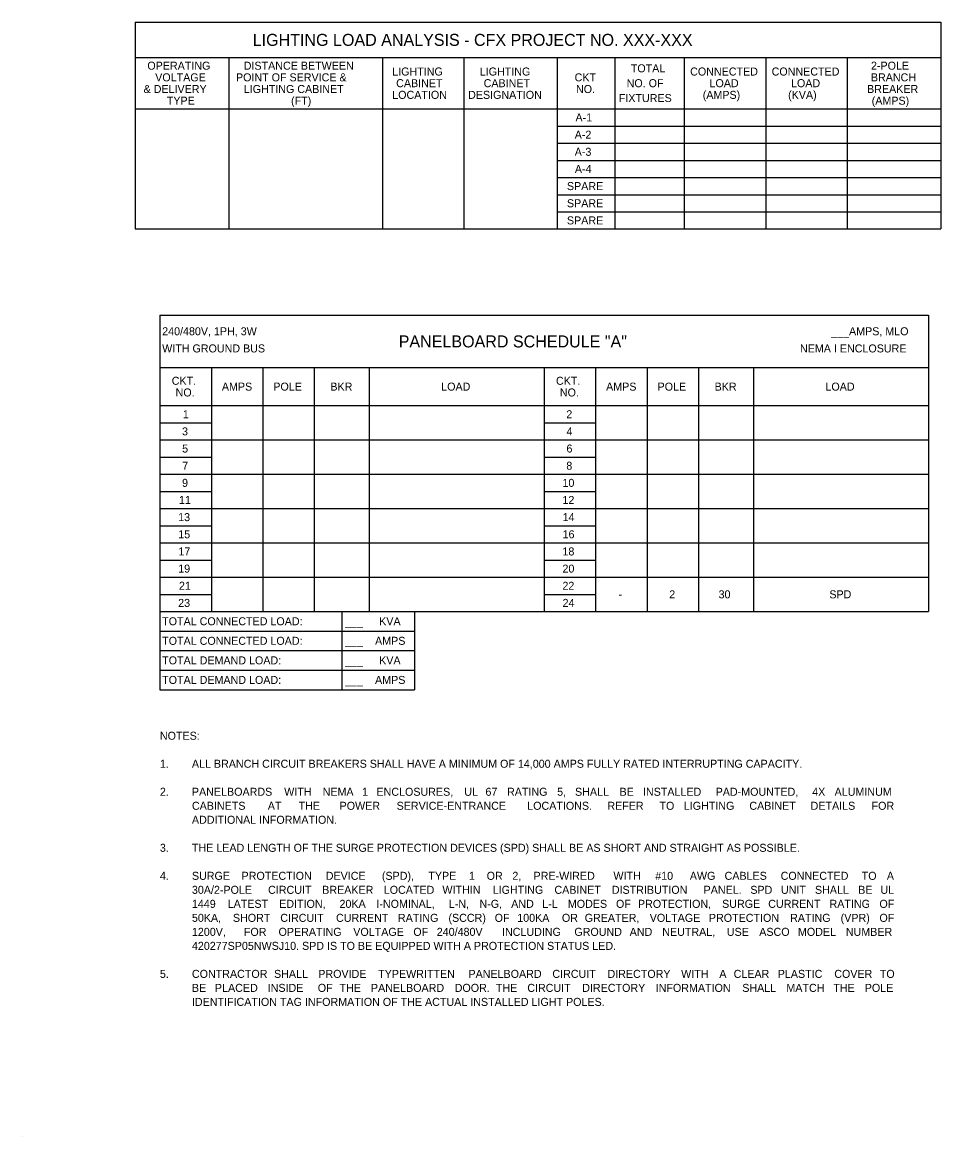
# Model space of a CAD drawing. Extents: x 856079 to 2148480, y 462635 to 2147771.
# Drawn here: x 2148464.67 to 2148472.7, y 2147761.57 to 2147771.31 of the extents above; entities that cross this region are included whole.
import ezdxf

# ---------------------------------------------------------------- set-up
doc = ezdxf.new("R2010")
doc.units = 0
for name, color, linetype in [('AdhocPoint_dp', 7, 'Continuous'), ('FLMap5', 7, 'Continuous'), ('SumBoxBorder_dp', 7, 'Continuous'), ('SumBoxLines_dp', 7, 'Continuous'), ('TextNotes', 7, 'Continuous')]:
    doc.layers.add(name, color=color, linetype=linetype)

msp = doc.modelspace()

# ---------------------------------------------------------------- linework, layer by layer
at = {"layer": 'AdhocPoint_dp'}
msp.add_line((2148464.6682, 2147761.5674), (2148464.6682, 2147761.5674), dxfattribs=at)
at = {"layer": 'SumBoxBorder_dp'}
for p, q in [((2148465.6565, 2147771.3129), (2148472.699, 2147771.3129)), ((2148465.6565, 2147771.3129), (2148465.6565, 2147769.5054)), ((2148472.699, 2147771.3129), (2148472.699, 2147769.5054)), ((2148465.6565, 2147771.0054), (2148472.699, 2147771.0054)), ((2148465.6565, 2147771.0054), (2148472.699, 2147771.0054)), ((2148465.6565, 2147769.5054), (2148472.699, 2147769.5054)), ((2148465.8715, 2147768.7509), (2148472.5915, 2147768.7509)), ((2148465.8715, 2147768.7509), (2148465.8715, 2147765.4764)), ((2148472.5915, 2147768.7509), (2148472.5915, 2147766.1604)), ((2148465.8715, 2147768.2934), (2148472.5915, 2147768.2934)), ((2148465.8715, 2147768.2934), (2148472.5915, 2147768.2934)), ((2148465.8715, 2147766.1604), (2148472.5915, 2147766.1604)), ((2148465.8715, 2147766.1604), (2148472.5915, 2147766.1604)), ((2148467.4615, 2147766.1604), (2148467.4615, 2147765.4764)), ((2148467.4615, 2147766.1604), (2148467.4615, 2147765.4764)), ((2148468.099, 2147766.1604), (2148468.099, 2147765.4764)), ((2148468.099, 2147766.1604), (2148468.099, 2147765.4764)), ((2148465.8715, 2147765.9894), (2148468.099, 2147765.9894)), ((2148465.8715, 2147765.9894), (2148468.099, 2147765.9894)), ((2148465.8715, 2147765.8184), (2148468.099, 2147765.8184)), ((2148465.8715, 2147765.8184), (2148468.099, 2147765.8184)), ((2148465.8715, 2147765.6474), (2148468.099, 2147765.6474)), ((2148465.8715, 2147765.6474), (2148468.099, 2147765.6474)), ((2148465.8715, 2147765.4764), (2148468.099, 2147765.4764))]:
    msp.add_line(p, q, dxfattribs=at)
at = {"layer": 'SumBoxLines_dp'}
for p, q in [((2148466.474, 2147771.0054), (2148466.474, 2147769.5054)), ((2148466.474, 2147771.0054), (2148466.474, 2147769.5054)), ((2148467.8165, 2147771.0054), (2148467.8165, 2147769.5054)), ((2148467.8165, 2147771.0054), (2148467.8165, 2147769.5054)), ((2148468.529, 2147771.0054), (2148468.529, 2147769.5054)), ((2148468.529, 2147771.0054), (2148468.529, 2147769.5054)), ((2148469.3465, 2147771.0054), (2148469.3465, 2147769.5054)), ((2148469.3465, 2147771.0054), (2148469.3465, 2147769.5054)), ((2148469.849, 2147771.0054), (2148469.849, 2147769.5054)), ((2148469.849, 2147771.0054), (2148469.849, 2147769.5054)), ((2148470.4565, 2147771.0054), (2148470.4565, 2147769.5054)), ((2148470.4565, 2147771.0054), (2148470.4565, 2147769.5054)), ((2148471.169, 2147771.0054), (2148471.169, 2147769.5054)), ((2148471.169, 2147771.0054), (2148471.169, 2147769.5054)), ((2148471.8815, 2147771.0054), (2148471.8815, 2147769.5054)), ((2148471.8815, 2147771.0054), (2148471.8815, 2147769.5054)), ((2148465.6565, 2147770.5554), (2148472.699, 2147770.5554)), ((2148465.6565, 2147770.5554), (2148472.699, 2147770.5554)), ((2148469.3465, 2147770.4054), (2148472.699, 2147770.4054)), ((2148469.3465, 2147770.4054), (2148472.699, 2147770.4054)), ((2148469.3465, 2147770.2554), (2148472.699, 2147770.2554)), ((2148469.3465, 2147770.2554), (2148472.699, 2147770.2554)), ((2148469.3465, 2147770.1054), (2148472.699, 2147770.1054)), ((2148469.3465, 2147770.1054), (2148472.699, 2147770.1054)), ((2148469.3465, 2147769.9554), (2148472.699, 2147769.9554)), ((2148469.3465, 2147769.9554), (2148472.699, 2147769.9554)), ((2148469.3465, 2147769.8054), (2148472.699, 2147769.8054)), ((2148469.3465, 2147769.8054), (2148472.699, 2147769.8054)), ((2148469.3465, 2147769.6554), (2148472.699, 2147769.6554)), ((2148469.3465, 2147769.6554), (2148472.699, 2147769.6554)), ((2148466.3215, 2147768.2934), (2148466.3215, 2147766.1604)), ((2148466.3215, 2147768.2934), (2148466.3215, 2147766.1604)), ((2148466.7715, 2147768.2934), (2148466.7715, 2147766.1604)), ((2148466.7715, 2147768.2934), (2148466.7715, 2147766.1604)), ((2148467.2215, 2147768.2934), (2148467.2215, 2147766.1604)), ((2148467.2215, 2147768.2934), (2148467.2215, 2147766.1604)), ((2148467.7015, 2147768.2934), (2148467.7015, 2147766.1604)), ((2148467.7015, 2147768.2934), (2148467.7015, 2147766.1604)), ((2148469.2315, 2147768.2934), (2148469.2315, 2147766.1604)), ((2148469.6815, 2147768.2934), (2148469.6815, 2147766.1604)), ((2148469.6815, 2147768.2934), (2148469.6815, 2147766.1604)), ((2148470.1315, 2147768.2934), (2148470.1315, 2147766.1604)), ((2148470.1315, 2147768.2934), (2148470.1315, 2147766.1604)), ((2148470.5815, 2147768.2934), (2148470.5815, 2147766.1604)), ((2148470.5815, 2147768.2934), (2148470.5815, 2147766.1604)), ((2148471.0615, 2147768.2934), (2148471.0615, 2147766.1604)), ((2148471.0615, 2147768.2934), (2148471.0615, 2147766.1604)), ((2148465.8715, 2147767.9604), (2148472.5915, 2147767.9604)), ((2148465.8715, 2147767.9604), (2148472.5915, 2147767.9604)), ((2148469.2315, 2147767.9604), (2148469.2315, 2147766.1604)), ((2148465.8715, 2147767.8104), (2148466.3215, 2147767.8104)), ((2148469.2315, 2147767.8104), (2148469.6815, 2147767.8104)), ((2148465.8715, 2147767.6604), (2148472.5915, 2147767.6604)), ((2148465.8715, 2147767.6604), (2148472.5915, 2147767.6604)), ((2148465.8715, 2147767.5104), (2148466.3215, 2147767.5104)), ((2148465.8715, 2147767.5104), (2148466.3215, 2147767.5104)), ((2148469.2315, 2147767.5104), (2148469.6815, 2147767.5104)), ((2148469.2315, 2147767.5104), (2148469.6815, 2147767.5104)), ((2148465.8715, 2147767.3604), (2148472.5915, 2147767.3604)), ((2148466.3215, 2147767.3604), (2148469.2315, 2147767.3604)), ((2148469.6815, 2147767.3604), (2148472.5915, 2147767.3604)), ((2148465.8715, 2147767.2104), (2148466.3215, 2147767.2104)), ((2148465.8715, 2147767.2104), (2148466.3215, 2147767.2104)), ((2148469.2315, 2147767.2104), (2148469.6815, 2147767.2104)), ((2148469.2315, 2147767.2104), (2148469.6815, 2147767.2104)), ((2148465.8715, 2147767.0604), (2148472.5915, 2147767.0604)), ((2148465.8715, 2147767.0604), (2148472.5915, 2147767.0604)), ((2148465.8715, 2147766.9104), (2148466.3215, 2147766.9104)), ((2148469.2315, 2147766.9104), (2148469.6815, 2147766.9104)), ((2148465.8715, 2147766.7604), (2148472.5915, 2147766.7604)), ((2148465.8715, 2147766.7604), (2148472.5915, 2147766.7604)), ((2148465.8715, 2147766.6104), (2148466.3215, 2147766.6104)), ((2148465.8715, 2147766.6104), (2148466.3215, 2147766.6104)), ((2148469.2315, 2147766.6104), (2148469.6815, 2147766.6104)), ((2148469.2315, 2147766.6104), (2148469.6815, 2147766.6104)), ((2148465.8715, 2147766.4604), (2148472.5915, 2147766.4604)), ((2148466.3215, 2147766.4604), (2148469.2315, 2147766.4604)), ((2148469.6815, 2147766.4604), (2148472.5915, 2147766.4604)), ((2148465.8715, 2147766.3104), (2148466.3215, 2147766.3104)), ((2148465.8715, 2147766.3104), (2148466.3215, 2147766.3104)), ((2148469.2315, 2147766.3104), (2148469.6815, 2147766.3104)), ((2148469.2315, 2147766.3104), (2148469.6815, 2147766.3104))]:
    msp.add_line(p, q, dxfattribs=at)

# ---------------------------------------------------------------- texts
at = {"layer": 'FLMap5'}
for s, height, p in [('LIGHTING LOAD ANALYSIS - CFX PROJECT NO. XXX-XXX', 0.105, (2148466.6829, 2147771.1067)), ('OPERATING', 0.07, (2148465.7617, 2147770.8984)), ('DISTANCE BETWEEN', 0.07, (2148466.6045, 2147770.8984)), ('LIGHTING', 0.07, (2148467.9031, 2147770.8474)), ('LIGHTING', 0.07, (2148468.6681, 2147770.8474)), ('TOTAL', 0.07, (2148469.9891, 2147770.8754)), ('CONNECTED', 0.07, (2148470.5081, 2147770.8474)), ('CONNECTED', 0.07, (2148471.2206, 2147770.8474)), ('2-POLE', 0.07, (2148472.0893, 2147770.8984)), ('VOLTAGE', 0.07, (2148465.8304, 2147770.7964)), ('POINT OF SERVICE &', 0.07, (2148466.5368, 2147770.7964)), ('CABINET', 0.07, (2148467.9374, 2147770.7454)), ('CABINET', 0.07, (2148468.7024, 2147770.7454)), ('CKT', 0.07, (2148469.4979, 2147770.7964)), ('NO. OF', 0.07, (2148469.9528, 2147770.7454)), ('LOAD', 0.07, (2148470.6775, 2147770.7454)), ('LOAD', 0.07, (2148471.39, 2147770.7454)), ('BRANCH', 0.07, (2148472.0883, 2147770.7964)), ('& DELIVERY', 0.07, (2148465.7289, 2147770.6944)), ('LIGHTING CABINET', 0.07, (2148466.605, 2147770.6944)), ('LOCATION', 0.07, (2148467.9031, 2147770.6434)), ('DESIGNATION', 0.07, (2148468.5664, 2147770.6434)), ('NO.', 0.07, (2148469.5101, 2147770.6944)), ('(AMPS)', 0.07, (2148470.6182, 2147770.6434)), ('(KVA)', 0.07, (2148471.3646, 2147770.6434)), ('BREAKER', 0.07, (2148472.0553, 2147770.6944)), ('TYPE', 0.07, (2148465.932, 2147770.5924)), ('(FT)', 0.07, (2148467.0184, 2147770.5924)), ('FIXTURES', 0.07, (2148469.8842, 2147770.6154)), ('(AMPS)', 0.07, (2148472.0957, 2147770.5924)), ('A-1', 0.07, (2148469.5054, 2147770.4454)), ('A-2', 0.07, (2148469.4986, 2147770.2954)), ('A-3', 0.07, (2148469.4986, 2147770.1454)), ('A-4', 0.07, (2148469.5, 2147769.9954)), ('SPARE', 0.07, (2148469.4306, 2147769.8454)), ('SPARE', 0.07, (2148469.4306, 2147769.6954)), ('SPARE', 0.07, (2148469.4306, 2147769.5454)), ('240/480V, 1PH, 3W', 0.07, (2148465.8915, 2147768.5759)), ('___AMPS, MLO', 0.07, (2148471.7412, 2147768.5759)), ('PANELBOARD SCHEDULE "A"', 0.105, (2148467.9596, 2147768.4697)), ('WITH GROUND BUS', 0.07, (2148465.8915, 2147768.4259)), ('NEMA I ENCLOSURE', 0.07, (2148471.4688, 2147768.4259)), ('CKT.', 0.07, (2148465.975, 2147768.1429)), ('AMPS', 0.07, (2148466.4134, 2147768.0919)), ('POLE', 0.07, (2148466.8633, 2147768.0919)), ('BKR', 0.07, (2148467.3621, 2147768.0919)), ('LOAD', 0.07, (2148468.3313, 2147768.0919)), ('CKT.', 0.07, (2148469.335, 2147768.1429)), ('AMPS', 0.07, (2148469.7734, 2147768.0919)), ('POLE', 0.07, (2148470.2233, 2147768.0919)), ('BKR', 0.07, (2148470.7221, 2147768.0919)), ('LOAD', 0.07, (2148471.6913, 2147768.0919)), ('NO.', 0.07, (2148466.0089, 2147768.0409)), ('NO.', 0.07, (2148469.3689, 2147768.0409)), ('1', 0.07, (2148466.0719, 2147767.8504)), ('2', 0.07, (2148469.4251, 2147767.8504)), ('3', 0.07, (2148466.0651, 2147767.7004)), ('4', 0.07, (2148469.4265, 2147767.7004)), ('5', 0.07, (2148466.066, 2147767.5504)), ('6', 0.07, (2148469.4265, 2147767.5504)), ('7', 0.07, (2148466.0671, 2147767.4004)), ('8', 0.07, (2148469.4254, 2147767.4004)), ('9', 0.07, (2148466.0655, 2147767.2504)), ('10', 0.07, (2148469.3918, 2147767.2504)), ('11', 0.07, (2148466.038, 2147767.1004)), ('12', 0.07, (2148469.3913, 2147767.1004)), ('13', 0.07, (2148466.0312, 2147766.9504)), ('14', 0.07, (2148469.3926, 2147766.9504)), ('15', 0.07, (2148466.0321, 2147766.8004)), ('16', 0.07, (2148469.3927, 2147766.8004)), ('17', 0.07, (2148466.0333, 2147766.6504)), ('18', 0.07, (2148469.3915, 2147766.6504)), ('19', 0.07, (2148466.0316, 2147766.5004)), ('20', 0.07, (2148469.3918, 2147766.5004)), ('21', 0.07, (2148466.038, 2147766.3504)), ('22', 0.07, (2148469.3913, 2147766.3504)), ('2', 0.07, (2148470.3251, 2147766.2754)), ('30', 0.07, (2148470.7568, 2147766.2754)), ('SPD', 0.07, (2148471.7252, 2147766.2754)), ('23', 0.07, (2148466.0312, 2147766.2004)), ('24', 0.07, (2148469.3926, 2147766.2004)), ('-', 0.07, (2148469.883, 2147766.2754)), ('TOTAL CONNECTED LOAD:', 0.07, (2148465.8915, 2147766.0399)), ('___', 0.07, (2148467.4905, 2147766.0399)), ('KVA', 0.07, (2148467.7889, 2147766.0399)), ('TOTAL CONNECTED LOAD:', 0.07, (2148465.8915, 2147765.8689)), ('AMPS', 0.07, (2148467.7529, 2147765.8689)), ('___', 0.07, (2148467.4905, 2147765.8689)), ('TOTAL DEMAND LOAD:', 0.07, (2148465.8915, 2147765.6979)), ('KVA', 0.07, (2148467.7889, 2147765.6979)), ('___', 0.07, (2148467.4905, 2147765.6979)), ('TOTAL DEMAND LOAD:', 0.07, (2148465.8915, 2147765.5269)), ('AMPS', 0.07, (2148467.7529, 2147765.5269)), ('___', 0.07, (2148467.4905, 2147765.5269))]:
    msp.add_text(s, height=height, dxfattribs=at).set_placement(p)
at = {"layer": 'TextNotes'}
for s, p in [('NOTES:', (2148465.8715, 2147765.0389)), ('1.', (2148465.8715, 2147764.7939)), ('ALL BRANCH CIRCUIT BREAKERS SHALL HAVE A MINIMUM OF 14,000 AMPS FULLY RATED INTERRUPTING CAPACITY.', (2148466.1515, 2147764.7939)), ('2.', (2148465.8715, 2147764.5489)), ('PANELBOARDS ', (2148466.1515, 2147764.5489)), ('WITH ', (2148466.9584, 2147764.5489)), ('NEMA ', (2148467.2946, 2147764.5489)), ('1 ', (2148467.6395, 2147764.5489)), ('ENCLOSURES, ', (2148467.7652, 2147764.5489)), ('UL ', (2148468.5329, 2147764.5489)), ('67 ', (2148468.7183, 2147764.5489)), ('RATING ', (2148468.9068, 2147764.5489)), ('5, ', (2148469.3451, 2147764.5489)), ('SHALL ', (2148469.5014, 2147764.5489)), ('BE ', (2148469.8908, 2147764.5489)), ('INSTALLED ', (2148470.0957, 2147764.5489)), ('PAD-MOUNTED, ', (2148470.7311, 2147764.5489)), ('4X ', (2148471.5752, 2147764.5489)), ('ALUMINUM ', (2148471.7711, 2147764.5489)), ('CABINETS ', (2148466.1515, 2147764.4264)), ('AT ', (2148466.8149, 2147764.4264)), ('THE ', (2148467.085, 2147764.4264)), ('POWER ', (2148467.4429, 2147764.4264)), ('SERVICE-ENTRANCE ', (2148467.9412, 2147764.4264)), ('LOCATIONS. ', (2148469.0833, 2147764.4264)), (' REFER ', (2148469.758, 2147764.4264)), ('TO ', (2148470.2398, 2147764.4264)), ('LIGHTING ', (2148470.4525, 2147764.4264)), ('CABINET ', (2148471.0259, 2147764.4264)), ('DETAILS ', (2148471.5615, 2147764.4264)), ('FOR ', (2148472.0945, 2147764.4264)), ('ADDITIONAL INFORMATION.', (2148466.1515, 2147764.3039)), ('3.', (2148465.8715, 2147764.0589)), ('THE LEAD LENGTH OF THE SURGE PROTECTION DEVICES (SPD) SHALL BE AS SHORT AND STRAIGHT AS POSSIBLE.', (2148466.1515, 2147764.0589)), ('4.', (2148465.8715, 2147763.8139)), ('SURGE ', (2148466.1515, 2147763.8139)), ('PROTECTION ', (2148466.5857, 2147763.8139)), ('DEVICE ', (2148467.3218, 2147763.8139)), ('(SPD), ', (2148467.8126, 2147763.8139)), ('TYPE ', (2148468.2187, 2147763.8139)), ('1 ', (2148468.5739, 2147763.8139)), ('OR ', (2148468.7288, 2147763.8139)), ('2, ', (2148468.9534, 2147763.8139)), ('PRE-WIRED ', (2148469.1389, 2147763.8139)), ('WITH ', (2148469.8373, 2147763.8139)), ('#10 ', (2148470.2027, 2147763.8139)), ('AWG ', (2148470.5052, 2147763.8139)), ('CABLES ', (2148470.8091, 2147763.8139)), ('CONNECTED ', (2148471.2993, 2147763.8139)), ('TO ', (2148472.0084, 2147763.8139)), ('A ', (2148472.228, 2147763.8139)), ('30A/2-POLE ', (2148466.1515, 2147763.6914)), ('CIRCUIT ', (2148466.8177, 2147763.6914)), ('BREAKER ', (2148467.2908, 2147763.6914)), ('LOCATED ', (2148467.8292, 2147763.6914)), ('WITHIN ', (2148468.3419, 2147763.6914)), ('LIGHTING ', (2148468.7816, 2147763.6914)), ('CABINET ', (2148469.3214, 2147763.6914)), ('DISTRIBUTION ', (2148469.8234, 2147763.6914)), ('PANEL. ', (2148470.6259, 2147763.6914)), ('SPD ', (2148471.0342, 2147763.6914)), ('UNIT ', (2148471.3022, 2147763.6914)), ('SHALL ', (2148471.5994, 2147763.6914)), ('BE ', (2148471.9777, 2147763.6914)), ('UL ', (2148472.1716, 2147763.6914)), ('1449 ', (2148466.1515, 2147763.5689)), ('LATEST ', (2148466.4641, 2147763.5689)), ('EDITION, ', (2148466.9146, 2147763.5689)), ('20KA ', (2148467.442, 2147763.5689)), ('I-NOMINAL, ', (2148467.7646, 2147763.5689)), ('L-N, ', (2148468.398, 2147763.5689)), ('N-G, ', (2148468.6663, 2147763.5689)), ('AND ', (2148468.9432, 2147763.5689)), ('L-L ', (2148469.2148, 2147763.5689)), ('MODES ', (2148469.4386, 2147763.5689)), ('OF ', (2148469.8597, 2147763.5689)), ('PROTECTION, ', (2148470.0518, 2147763.5689)), ('SURGE ', (2148470.7875, 2147763.5689)), ('CURRENT ', (2148471.1908, 2147763.5689)), ('RATING ', (2148471.7267, 2147763.5689)), ('OF ', (2148472.1633, 2147763.5689)), ('50KA, ', (2148466.1515, 2147763.4464)), ('SHORT ', (2148466.5099, 2147763.4464)), ('CIRCUIT ', (2148466.924, 2147763.4464)), ('CURRENT ', (2148467.4118, 2147763.4464)), ('RATING ', (2148467.9528, 2147763.4464)), ('(SCCR) ', (2148468.3946, 2147763.4464)), ('OF ', (2148468.7989, 2147763.4464)), ('100KA ', (2148468.9961, 2147763.4464)), ('OR ', (2148469.3867, 2147763.4464)), ('GREATER, ', (2148469.5856, 2147763.4464)), ('VOLTAGE ', (2148470.1548, 2147763.4464)), ('PROTECTION ', (2148470.672, 2147763.4464)), ('RATING ', (2148471.3823, 2147763.4464)), ('(VPR) ', (2148471.8241, 2147763.4464)), ('OF ', (2148472.1633, 2147763.4464)), ('1200V, ', (2148466.1515, 2147763.3239)), ('FOR ', (2148466.6057, 2147763.3239)), ('OPERATING ', (2148466.9091, 2147763.3239)), ('VOLTAGE ', (2148467.5624, 2147763.3239)), ('OF ', (2148468.0874, 2147763.3239)), ('240/480V ', (2148468.2925, 2147763.3239)), ('INCLUDING ', (2148468.863, 2147763.3239)), ('GROUND ', (2148469.4956, 2147763.3239)), ('AND ', (2148469.9796, 2147763.3239)), ('NEUTRAL, ', (2148470.2642, 2147763.3239)), ('USE ', (2148470.8289, 2147763.3239)), ('ASCO ', (2148471.1123, 2147763.3239)), ('MODEL ', (2148471.4507, 2147763.3239)), ('NUMBER ', (2148471.8695, 2147763.3239)), ('420277SP05NWSJ10. SPD IS TO BE EQUIPPED WITH A PROTECTION STATUS LED.', (2148466.1515, 2147763.2014)), ('5.', (2148465.8715, 2147762.9564)), ('CONTRACTOR ', (2148466.1515, 2147762.9564)), ('SHALL ', (2148466.8693, 2147762.9564)), ('PROVIDE ', (2148467.2565, 2147762.9564)), ('TYPEWRITTEN ', (2148467.78, 2147762.9564)), ('PANELBOARD ', (2148468.5695, 2147762.9564)), ('CIRCUIT ', (2148469.3034, 2147762.9564)), ('DIRECTORY ', (2148469.7854, 2147762.9564)), ('WITH ', (2148470.4294, 2147762.9564)), ('A ', (2148470.7633, 2147762.9564)), ('CLEAR ', (2148470.8881, 2147762.9564)), ('PLASTIC ', (2148471.274, 2147762.9564)), ('COVER ', (2148471.7683, 2147762.9564)), ('TO ', (2148472.1667, 2147762.9564)), ('BE ', (2148466.1515, 2147762.8339)), ('PLACED ', (2148466.3528, 2147762.8339)), ('INSIDE ', (2148466.814, 2147762.8339)), ('OF ', (2148467.2521, 2147762.8339)), ('THE ', (2148467.442, 2147762.8339)), ('PANELBOARD ', (2148467.7169, 2147762.8339)), ('DOOR. ', (2148468.4493, 2147762.8339)), ('THE ', (2148468.809, 2147762.8339)), ('CIRCUIT ', (2148469.0839, 2147762.8339)), ('DIRECTORY ', (2148469.5644, 2147762.8339)), ('INFORMATION ', (2148470.2069, 2147762.8339)), ('SHALL ', (2148470.9638, 2147762.8339)), ('MATCH ', (2148471.3495, 2147762.8339)), ('THE ', (2148471.7601, 2147762.8339)), ('POLE ', (2148472.035, 2147762.8339)), ('IDENTIFICATION TAG INFORMATION OF THE ACTUAL INSTALLED LIGHT POLES.', (2148466.1515, 2147762.7114))]:
    msp.add_text(s, height=0.07, dxfattribs=at).set_placement(p)

doc.saveas('drawing.dxf')
